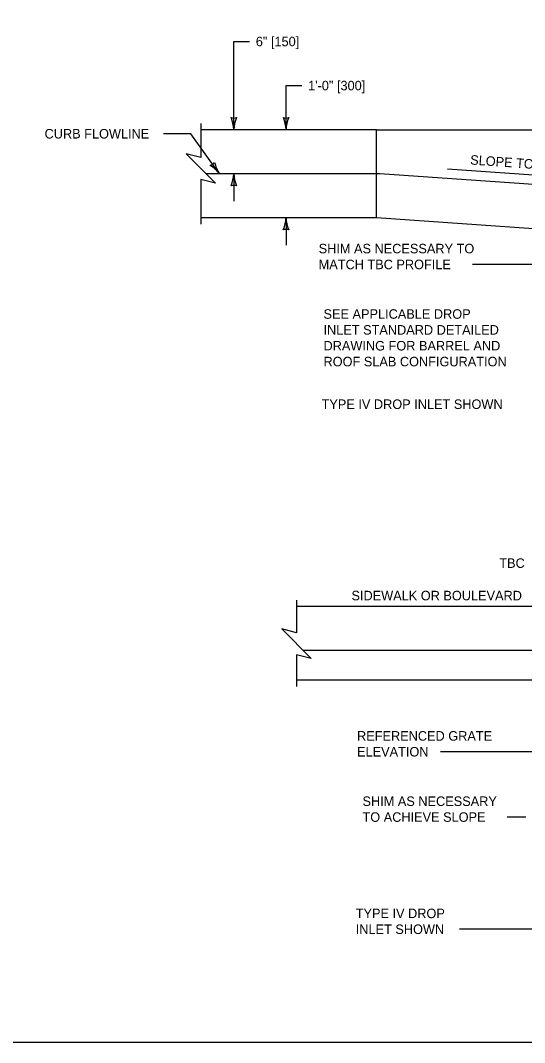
# Model space of a CAD drawing. Extents: x 49991.4 to 50048.3, y 49987.6 to 50018.3.
# Drawn here: x 50004.04 to 50007.22, y 49987.8 to 49994.24 of the extents above; entities that cross this region are included whole.
import ezdxf

# ---------------------------------------------------------------- set-up
doc = ezdxf.new("R2010")
doc.units = 0
for name, color, linetype in [('Level 1', 7, 'Continuous'), ('Level 2', 7, 'Continuous'), ('Level 3', 7, 'Continuous'), ('Level 6', 7, 'Continuous')]:
    doc.layers.add(name, color=color, linetype=linetype)

msp = doc.modelspace()

# ---------------------------------------------------------------- linework, layer by layer
at = {"layer": 'Level 1'}
for p, q in [((50006.2842, 49993.5547), (50005.1765, 49993.5547)), ((50006.2842, 49992.9997), (50006.2842, 49993.5547)), ((50006.2842, 49993.5547), (50010.9017, 49993.5547)), ((50006.3036, 49993.2772), (50005.2086, 49993.2772)), ((50007.9687, 49993.1608), (50006.3036, 49993.2772)), ((50006.2842, 49992.9997), (50005.1765, 49992.9997)), ((50007.7825, 49992.8949), (50006.2842, 49992.9997)), ((50007.5058, 49990.5488), (50005.7794, 49990.5488)), ((50007.5058, 49990.2704), (50005.8228, 49990.2704)), ((50006.9652, 49990.0848), (50005.7794, 49990.0848)), ((50007.5058, 49990.0848), (50006.9652, 49990.0848))]:
    msp.add_line(p, q, dxfattribs=at)
msp.add_lwpolyline([(49999.3835, 49998.9992), (50016.7501, 49998.9992), (50016.7501, 49987.7988), (49999.3835, 49987.7988)], close=True, dxfattribs=at)
at = {"layer": 'Level 3'}
for p, q in [((50005.3836, 49993.5547), (50005.3836, 49994.111)), ((50005.7131, 49993.5547), (50005.7131, 49993.8329)), ((50005.2938, 49993.2772), (50005.114, 49993.5291)), ((50005.3836, 49993.2772), (50005.3836, 49993.1038)), ((50007.8062, 49993.2303), (50006.7304, 49993.3055)), ((50005.7131, 49992.9997), (50005.7131, 49992.8263)), ((50007.468, 49992.7051), (50006.8881, 49992.7051)), ((50007.3651, 49989.6325), (50006.6868, 49989.6325)), ((50007.2241, 49989.2206), (50007.1063, 49989.2206)), ((50007.5773, 49988.5133), (50006.8068, 49988.5133))]:
    msp.add_line(p, q, dxfattribs=at)
for points in [[(50005.3836, 49994.111), (50005.4827, 49994.111), (50005.4827, 49994.111)], [(50005.7131, 49993.8329), (50005.8122, 49993.8329), (50005.8122, 49993.8329)], [(50005.114, 49993.5291), (50004.9398, 49993.5291), (50004.9398, 49993.5291)]]:
    msp.add_lwpolyline(points, dxfattribs=at)
for centre, radius, start, end in [((50005.3836, 49993.6829), 0.0548, 252.13882, 287.86118), ((50005.1509, 49993.5432), 0.233, 2.82731, 22.07716), ((50005.6058, 49993.5456), 0.2223, 157.45601, 177.63952), ((50005.7131, 49993.6829), 0.0548, 252.13882, 287.86118), ((50005.4804, 49993.5432), 0.233, 2.82731, 22.07716), ((50005.9352, 49993.5456), 0.2223, 157.45601, 177.63952), ((50005.2193, 49993.3816), 0.0548, 287.66315, 323.38551), ((50005.4799, 49993.3988), 0.2223, 192.98034, 213.16385), ((50005.1111, 49993.1327), 0.233, 38.35164, 57.60149), ((50005.1615, 49993.2864), 0.2223, 337.45601, 357.63952), ((50005.6164, 49993.2887), 0.233, 182.82731, 202.07716), ((50005.3836, 49993.149), 0.0548, 72.13882, 107.86118), ((50005.4909, 49993.0089), 0.2223, 337.45601, 357.63952), ((50005.9458, 49993.0112), 0.233, 182.82731, 202.07716), ((50005.7131, 49992.8715), 0.0548, 72.13882, 107.86118)]:
    msp.add_arc(centre, radius, start, end, dxfattribs=at)
at = {"layer": 'Level 6'}
for points in [[(50005.1765, 49993.5947), (50005.1765, 49993.3789), (50005.0838, 49993.4021), (50005.2692, 49993.2166), (50005.1765, 49993.2398), (50005.1765, 49992.9597)], [(50005.7794, 49990.5888), (50005.7794, 49990.3833), (50005.6867, 49990.4065), (50005.8722, 49990.221), (50005.7794, 49990.2442), (50005.7794, 49990.0448)]]:
    msp.add_lwpolyline(points, dxfattribs=at)

# ---------------------------------------------------------------- texts
at = {"layer": 'Level 2'}
for s, p in [('6" [150]', (50005.5227, 49994.081)), ('1\'-0" [300]', (50005.8522, 49993.8029)), ('CURB FLOWLINE', (50004.1912, 49993.4991)), ('SHIM AS NECESSARY TO', (50005.9189, 49992.7751)), ('MATCH TBC PROFILE', (50005.9189, 49992.6751)), ('SEE APPLICABLE DROP ', (50005.9495, 49992.3626)), ('INLET STANDARD DETAILED', (50005.9495, 49992.2626)), ('DRAWING FOR BARREL AND', (50005.9495, 49992.1626)), ('ROOF SLAB CONFIGURATION', (50005.9495, 49992.0626)), ('TYPE IV DROP INLET SHOWN', (50005.9373, 49991.794)), ('TBC', (50007.0577, 49990.7918)), ('SIDEWALK OR BOULEVARD', (50006.1258, 49990.5873)), ('REFERENCED GRATE', (50006.161, 49989.7025)), ('ELEVATION', (50006.161, 49989.6025)), ('SHIM AS NECESSARY', (50006.1952, 49989.2906)), ('TO ACHIEVE SLOPE', (50006.1952, 49989.1906)), ('TYPE IV DROP', (50006.1527, 49988.5833)), ('INLET SHOWN', (50006.1527, 49988.4833))]:
    msp.add_text(s, height=0.06, dxfattribs=at).set_placement(p)
msp.add_text('SLOPE TO INLET', height=0.06, rotation=356, dxfattribs=at).set_placement((50006.8726, 49993.3356))

doc.saveas('drawing.dxf')
